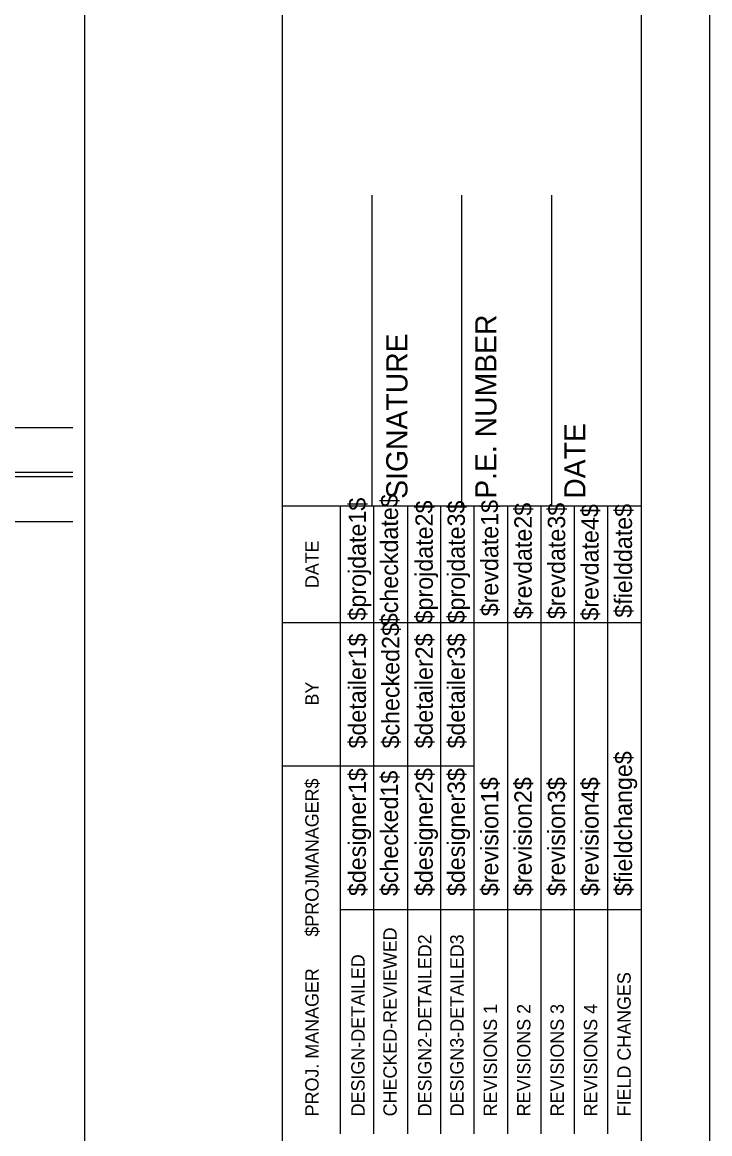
# Model space of a CAD drawing. Extents: x 1100953.92 to 1100956.78, y 416755.57 to 416757.4.
# Drawn here: x 1100956.434 to 1100956.753, y 416756.372 to 416756.888 of the extents above; entities that cross this region are included whole.
import ezdxf

# ---------------------------------------------------------------- set-up
doc = ezdxf.new("R2010")
doc.units = 0
for name, color, linetype in [('BORDER', 7, 'Continuous'), ('H_V CNTRL TEXT', 7, 'Continuous'), ('ORIG TOPO TEXT', 7, 'Continuous'), ('PLOT BOUNDARY', 7, 'Continuous')]:
    doc.layers.add(name, color=color, linetype=linetype)

msp = doc.modelspace()

# ---------------------------------------------------------------- linework, layer by layer
at = {"layer": 'BORDER'}
for p, q in [((1100956.55493, 416755.62172), (1100956.55493, 416757.37172)), ((1100956.72159, 416755.62172), (1100956.72159, 416757.37172)), ((1100956.59659, 416756.66338), (1100956.59659, 416756.80751)), ((1100956.63826, 416756.66338), (1100956.63826, 416756.80751)), ((1100956.67993, 416756.66338), (1100956.67993, 416756.80751)), ((1100956.55493, 416756.66338), (1100956.72159, 416756.66338))]:
    msp.add_line(p, q, dxfattribs=at)
for points in [[(1100956.58184, 416756.60922), (1100956.58184, 416756.66338)], [(1100956.59738, 416756.37177), (1100956.59738, 416756.66338)], [(1100956.61291, 416756.66338), (1100956.61291, 416756.37177)], [(1100956.62844, 416756.37177), (1100956.62844, 416756.66338)], [(1100956.64397, 416756.37177), (1100956.64397, 416756.66338)], [(1100956.6595, 416756.37177), (1100956.6595, 416756.66338)], [(1100956.67503, 416756.37177), (1100956.67503, 416756.66338)], [(1100956.69055, 416756.37177), (1100956.69055, 416756.66338)], [(1100956.70608, 416756.37177), (1100956.70608, 416756.66338)], [(1100956.58186, 416756.37177), (1100956.58186, 416756.65162)], [(1100956.55493, 416756.60922), (1100956.72159, 416756.60922)], [(1100956.55493, 416756.54255), (1100956.58186, 416756.54255)], [(1100956.58184, 416756.54255), (1100956.64395, 416756.54255)], [(1100956.58184, 416756.47588), (1100956.72159, 416756.47588)]]:
    msp.add_lwpolyline(points, dxfattribs=at)
at = {"layer": 'H_V CNTRL TEXT'}
for p, q in [((1100956.27473, 416756.69969), (1100956.45743, 416756.69969)), ((1100956.45743, 416756.67677), (1100956.26524, 416756.67677)), ((1100956.45743, 416756.67885), (1100956.2661, 416756.67885)), ((1100956.45743, 416756.65594), (1100956.25661, 416756.65594))]:
    msp.add_line(p, q, dxfattribs=at)
at = {"layer": 'ORIG TOPO TEXT'}
msp.add_lwpolyline([(1100955.83565, 416756.95507), (1100955.83565, 416756.3569), (1100956.46304, 416756.3569), (1100956.46304, 416756.95507), (1100955.83565, 416756.95507)], dxfattribs=at)
at = {"layer": 'PLOT BOUNDARY'}
msp.add_lwpolyline([(1100953.92004, 416755.57068), (1100956.75337, 416755.57068), (1100956.75337, 416757.40402), (1100953.92004, 416757.40402)], close=True, dxfattribs=at)

# ---------------------------------------------------------------- texts
at = {"layer": 'BORDER'}
for s, height, p in [('P.E. NUMBER', 0.0098425, (1100956.65427, 416756.66659)), ('SIGNATURE', 0.009843, (1100956.61293, 416756.66659)), ('DATE', 0.009843, (1100956.69561, 416756.66659)), ('$projdate1$', 0.0080758, (1100956.59364, 416756.61005)), ('$checkdate$', 0.0080758, (1100956.60855, 416756.60743)), ('$projdate2$', 0.0080758, (1100956.6247, 416756.60874)), ('$projdate3$', 0.0080758, (1100956.63961, 416756.60874)), ('$revdate1$', 0.008076, (1100956.65513, 416756.61202)), ('$revdate2$', 0.008076, (1100956.67066, 416756.61071)), ('$revdate3$', 0.008076, (1100956.68619, 416756.61071)), ('$revdate4$', 0.008076, (1100956.70172, 416756.61005)), ('$fielddate$', 0.0080758, (1100956.71725, 416756.61137)), ('DATE', 0.00619, (1100956.57167, 416756.62515)), ('$checked2$', 0.008076, (1100956.60917, 416756.55064)), ('$detailer1$', 0.0080758, (1100956.59364, 416756.55064)), ('$detailer2$', 0.0080758, (1100956.6247, 416756.55064)), ('$detailer3$', 0.0080758, (1100956.63961, 416756.55064)), ('BY', 0.00619, (1100956.57167, 416756.57063)), ('$fieldchange$', 0.0080758, (1100956.71725, 416756.4821)), ('$designer1$', 0.0080758, (1100956.59364, 416756.4821)), ('$designer2$', 0.0080758, (1100956.6247, 416756.4821)), ('$designer3$', 0.0080758, (1100956.63961, 416756.4821)), ('$PROJMANAGER$', 0.0062125, (1100956.57167, 416756.4633)), ('$checked1$', 0.008076, (1100956.60855, 416756.4821)), ('$revision1$', 0.0080758, (1100956.65513, 416756.4821)), ('$revision2$', 0.0080758, (1100956.67066, 416756.4821)), ('$revision3$', 0.0080758, (1100956.68619, 416756.4821)), ('$revision4$', 0.0080758, (1100956.70172, 416756.4821)), ('CHECKED-REVIEWED', 0.0062125, (1100956.60794, 416756.37985)), ('DESIGN2-DETAILED2', 0.0062125, (1100956.62409, 416756.37985)), ('DESIGN3-DETAILED3', 0.0062125, (1100956.639, 416756.37985)), ('DESIGN-DETAILED', 0.0062125, (1100956.59304, 416756.37985)), ('PROJ. MANAGER', 0.0062125, (1100956.57167, 416756.37985)), ('FIELD CHANGES', 0.0062125, (1100956.71664, 416756.37985)), ('REVISIONS 1', 0.0062125, (1100956.65453, 416756.37985)), ('REVISIONS 2', 0.0062125, (1100956.67006, 416756.37985)), ('REVISIONS 3', 0.0062125, (1100956.68558, 416756.37985)), ('REVISIONS 4', 0.0062125, (1100956.70111, 416756.37985))]:
    msp.add_text(s, height=height, rotation=90, dxfattribs=at).set_placement(p)

doc.saveas('drawing.dxf')
